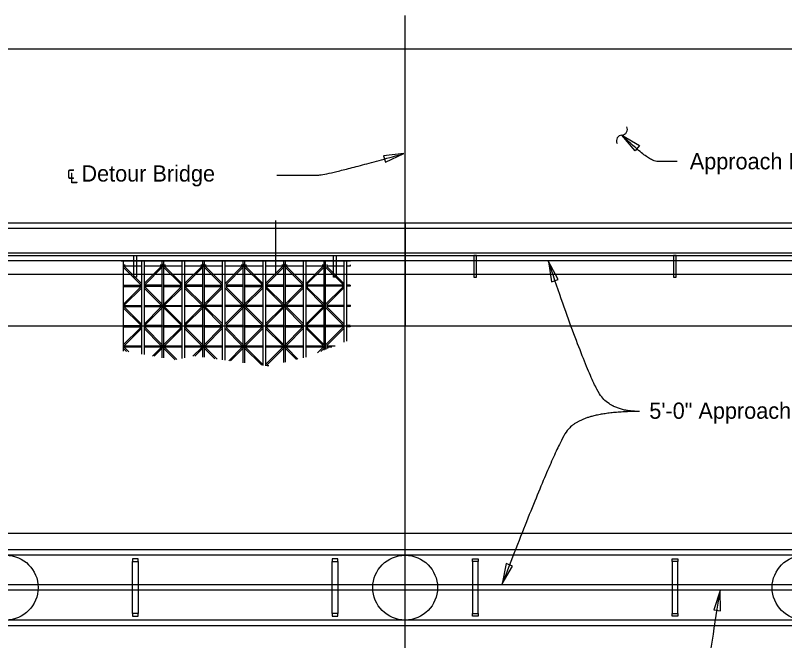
# Model space of a CAD drawing. Extents: x -58 to 62, y 0 to 81.
# Drawn here: x 24.75 to 36.63, y 29.48 to 39.13 of the extents above; entities that cross this region are included whole.
import ezdxf

# ---------------------------------------------------------------- set-up
doc = ezdxf.new("R2010")
doc.units = 0
for name, color, linetype in [('CL_Minor', 7, 'Continuous'), ('Dimension', 7, 'Continuous'), ('SteelMisc', 7, 'Continuous'), ('SteelMisc_h', 7, 'Continuous'), ('Symbols', 7, 'Continuous'), ('TextStructures', 7, 'Continuous'), ('Wood_h', 7, 'Continuous')]:
    doc.layers.add(name, color=color, linetype=linetype)

msp = doc.modelspace()

# ---------------------------------------------------------------- linework, layer by layer
at = {"layer": 'CL_Minor'}
msp.add_lwpolyline([(30.77, 7.919), (30.77, 34.382), (30.77, 39.134)], dxfattribs=at)
at = {"layer": 'Dimension'}
for points in [[(34.321, 37.043), (34.118, 37.286), (34.39, 37.124)], [(30.752, 37.001), (30.437, 36.968), (30.465, 36.866)], [(32.982, 35.336), (33.032, 35.023), (33.132, 35.057)], [(32.269, 30.361), (32.43, 30.634), (32.331, 30.672)], [(35.633, 30.258), (35.534, 29.957), (35.638, 29.941)]]:
    msp.add_lwpolyline(points, close=True, dxfattribs=at)
for centre, start, end in [((34.112, 37.376), 273.732, 25.4592), ((34.123, 37.197), 93.732, 205.4592)]:
    msp.add_arc(centre, 0.0894, start, end, dxfattribs=at)
for points in [[(34.972, 36.881), (34.787, 36.881), (34.531, 36.881), (34.118, 37.286)], [(28.788, 36.667), (29.264, 36.667), (29.554, 36.667), (30.752, 37.001)], [(34.391, 33.02), (33.994, 33.02), (33.616, 33.469), (32.982, 35.336)], [(34.391, 33.02), (33.466, 33.02), (33.052, 32.395), (32.269, 30.361)]]:
    msp.add_open_spline(points, degree=2, dxfattribs=at)
at = {"layer": 'SteelMisc'}
for p, q in [((30.77, 35.926), (30.77, 34.343)), ((18.53, 35.468), (43.009, 35.468)), ((42.77, 35.343), (19.989, 35.343)), ((30.77, 29.718), (30.77, 30.885)), ((42.77, 30.343), (18.77, 30.343)), ((42.77, 30.259), (18.77, 30.259))]:
    msp.add_line(p, q, dxfattribs=at)
msp.add_lwpolyline([(18.765, 35.843), (18.53, 35.843), (18.53, 35.426), (43.009, 35.426)], dxfattribs=at)
at = {"layer": 'SteelMisc_h'}
for p, q in [((26.387, 35.343), (29.926, 35.343)), ((26.416, 35.343), (26.416, 33.952)), ((26.436, 35.289), (26.436, 35.256)), ((26.697, 35.343), (26.697, 33.907)), ((26.738, 35.343), (26.738, 33.899)), ((26.999, 35.255), (26.999, 35.289)), ((27.02, 33.85), (27.02, 35.343)), ((27.02, 35.298), (27.02, 35.246)), ((27.041, 35.343), (27.041, 33.846)), ((27.061, 35.289), (27.061, 35.257)), ((27.322, 35.343), (27.322, 33.839)), ((27.363, 35.343), (27.363, 33.847)), ((27.624, 35.255), (27.624, 35.289)), ((27.645, 33.859), (27.645, 35.343)), ((27.645, 35.298), (27.645, 35.247)), ((27.666, 35.343), (27.666, 33.856)), ((27.686, 35.29), (27.686, 35.257)), ((27.947, 35.343), (27.947, 33.818)), ((27.988, 35.343), (27.988, 33.812)), ((28.249, 35.256), (28.249, 35.29)), ((28.27, 33.773), (28.27, 35.343)), ((28.27, 35.299), (28.27, 35.247)), ((28.291, 35.343), (28.291, 33.77)), ((28.311, 35.29), (28.311, 35.258)), ((28.572, 35.343), (28.572, 33.731)), ((28.613, 35.343), (28.613, 33.725)), ((28.874, 35.256), (28.874, 35.29)), ((28.895, 33.776), (28.895, 35.343)), ((28.895, 35.299), (28.895, 35.248)), ((28.916, 35.343), (28.916, 33.781)), ((28.936, 35.291), (28.936, 35.258)), ((29.197, 35.343), (29.197, 33.849)), ((29.238, 35.343), (29.238, 33.859)), ((29.499, 35.257), (29.499, 35.291)), ((29.52, 33.967), (29.52, 35.343)), ((29.52, 35.3), (29.52, 35.248)), ((29.541, 33.975), (29.541, 35.343)), ((29.541, 35.249), (29.541, 35.3)), ((29.561, 35.291), (29.561, 35.258)), ((29.822, 35.343), (29.822, 34.09)), ((29.863, 35.343), (29.863, 34.107)), ((29.921, 35.285), (29.921, 35.264)), ((26.416, 35.247), (26.676, 34.987)), ((26.698, 34.995), (26.436, 35.256)), ((26.696, 35.262), (26.438, 35.262)), ((26.996, 35.262), (26.737, 35.262)), ((26.739, 34.995), (26.999, 35.255)), ((26.759, 34.986), (27.02, 35.246)), ((27.02, 34.674), (27.02, 35.246)), ((27.041, 35.248), (27.301, 34.988)), ((27.323, 34.995), (27.061, 35.257)), ((27.321, 35.263), (27.063, 35.263)), ((27.621, 35.263), (27.362, 35.263)), ((27.364, 34.995), (27.624, 35.255)), ((27.384, 34.986), (27.645, 35.247)), ((27.645, 34.674), (27.645, 35.247)), ((27.666, 35.248), (27.926, 34.988)), ((27.948, 34.996), (27.686, 35.257)), ((27.946, 35.263), (27.688, 35.263)), ((28.246, 35.263), (27.987, 35.263)), ((27.989, 34.996), (28.249, 35.256)), ((28.009, 34.987), (28.27, 35.247)), ((28.27, 34.675), (28.27, 35.247)), ((28.291, 35.249), (28.551, 34.989)), ((28.573, 34.996), (28.311, 35.258)), ((28.571, 35.264), (28.313, 35.264)), ((28.871, 35.264), (28.612, 35.264)), ((28.614, 34.996), (28.874, 35.256)), ((28.634, 34.987), (28.895, 35.248)), ((28.895, 34.675), (28.895, 35.248)), ((28.916, 35.249), (29.176, 34.989)), ((29.198, 34.997), (28.936, 35.258)), ((29.196, 35.264), (28.938, 35.264)), ((29.496, 35.264), (29.237, 35.264)), ((29.239, 34.997), (29.499, 35.257)), ((29.259, 34.988), (29.52, 35.248)), ((29.52, 34.676), (29.52, 35.248)), ((29.801, 34.989), (29.541, 35.249)), ((29.822, 34.998), (29.561, 35.258)), ((29.824, 35.264), (29.562, 35.264)), ((29.921, 35.264), (29.863, 35.264)), ((26.676, 34.933), (26.416, 34.673)), ((26.417, 34.97), (26.675, 34.97)), ((26.42, 34.95), (26.677, 34.95)), ((26.697, 34.924), (26.436, 34.664)), ((26.676, 34.987), (26.676, 34.933)), ((26.739, 34.925), (26.999, 34.665)), ((26.759, 34.986), (26.759, 34.934)), ((27.02, 34.97), (26.759, 34.97)), ((26.759, 34.934), (27.02, 34.674)), ((27.018, 34.95), (26.76, 34.95)), ((27.301, 34.933), (27.041, 34.673)), ((27.042, 34.971), (27.3, 34.971)), ((27.045, 34.95), (27.302, 34.95)), ((27.322, 34.925), (27.061, 34.664)), ((27.301, 34.988), (27.301, 34.933)), ((27.364, 34.926), (27.624, 34.666)), ((27.384, 34.986), (27.384, 34.935)), ((27.645, 34.971), (27.384, 34.971)), ((27.384, 34.935), (27.645, 34.674)), ((27.643, 34.95), (27.385, 34.95)), ((27.926, 34.934), (27.666, 34.674)), ((27.667, 34.971), (27.925, 34.971)), ((27.67, 34.951), (27.927, 34.951)), ((27.947, 34.925), (27.686, 34.665)), ((27.926, 34.988), (27.926, 34.934)), ((27.989, 34.926), (28.249, 34.666)), ((28.009, 34.987), (28.009, 34.935)), ((28.27, 34.971), (28.009, 34.971)), ((28.009, 34.935), (28.27, 34.675)), ((28.268, 34.951), (28.01, 34.951)), ((28.551, 34.935), (28.291, 34.674)), ((28.292, 34.972), (28.55, 34.972)), ((28.295, 34.951), (28.552, 34.951)), ((28.572, 34.926), (28.311, 34.665)), ((28.551, 34.989), (28.551, 34.935)), ((28.614, 34.927), (28.874, 34.667)), ((28.634, 34.987), (28.634, 34.936)), ((28.895, 34.972), (28.634, 34.972)), ((28.634, 34.936), (28.895, 34.675)), ((28.893, 34.951), (28.635, 34.951)), ((29.176, 34.935), (28.916, 34.675)), ((28.917, 34.972), (29.175, 34.972)), ((28.92, 34.952), (29.177, 34.952)), ((29.197, 34.926), (28.936, 34.666)), ((29.176, 34.989), (29.176, 34.935)), ((29.239, 34.927), (29.499, 34.667)), ((29.259, 34.988), (29.259, 34.936)), ((29.52, 34.972), (29.259, 34.972)), ((29.259, 34.936), (29.52, 34.676)), ((29.518, 34.952), (29.26, 34.952)), ((29.801, 34.935), (29.541, 34.675)), ((29.797, 34.931), (29.541, 34.675)), ((29.8, 34.952), (29.544, 34.952)), ((29.799, 34.972), (29.545, 34.972)), ((29.823, 34.927), (29.561, 34.666)), ((29.801, 34.989), (29.801, 34.935)), ((29.921, 34.972), (29.863, 34.972)), ((29.921, 34.952), (29.864, 34.952)), ((29.921, 34.972), (29.921, 34.952)), ((26.416, 34.673), (26.492, 34.749)), ((27.041, 34.673), (27.117, 34.75)), ((27.666, 34.674), (27.742, 34.75)), ((28.291, 34.674), (28.367, 34.751)), ((28.916, 34.675), (28.992, 34.751)), ((26.416, 34.622), (26.676, 34.362)), ((26.436, 34.664), (26.436, 34.631)), ((26.698, 34.37), (26.436, 34.631)), ((26.438, 34.658), (26.697, 34.658)), ((26.696, 34.637), (26.438, 34.637)), ((26.996, 34.637), (26.737, 34.637)), ((26.739, 34.37), (26.999, 34.63)), ((26.74, 34.658), (27, 34.658)), ((26.759, 34.361), (27.02, 34.621)), ((26.999, 34.63), (26.999, 34.664)), ((27.02, 34.673), (27.02, 34.621)), ((27.02, 34.049), (27.02, 34.621)), ((27.041, 34.623), (27.301, 34.363)), ((27.061, 34.664), (27.061, 34.632)), ((27.323, 34.37), (27.061, 34.632)), ((27.063, 34.658), (27.322, 34.658)), ((27.321, 34.638), (27.063, 34.638)), ((27.621, 34.638), (27.362, 34.638)), ((27.364, 34.37), (27.624, 34.63)), ((27.365, 34.658), (27.625, 34.658)), ((27.384, 34.361), (27.645, 34.622)), ((27.624, 34.63), (27.624, 34.664)), ((27.645, 34.673), (27.645, 34.622)), ((27.645, 34.049), (27.645, 34.622)), ((27.666, 34.623), (27.926, 34.363)), ((27.686, 34.665), (27.686, 34.632)), ((27.948, 34.371), (27.686, 34.632)), ((27.688, 34.659), (27.947, 34.659)), ((27.946, 34.638), (27.688, 34.638)), ((28.246, 34.638), (27.987, 34.638)), ((27.989, 34.371), (28.249, 34.631)), ((27.99, 34.659), (28.25, 34.659)), ((28.009, 34.362), (28.27, 34.622)), ((28.249, 34.631), (28.249, 34.665)), ((28.27, 34.674), (28.27, 34.622)), ((28.27, 34.05), (28.27, 34.622)), ((28.291, 34.624), (28.551, 34.364)), ((28.311, 34.665), (28.311, 34.633)), ((28.573, 34.371), (28.311, 34.633)), ((28.313, 34.659), (28.572, 34.659)), ((28.571, 34.639), (28.313, 34.639)), ((28.871, 34.639), (28.612, 34.639)), ((28.614, 34.371), (28.874, 34.631)), ((28.615, 34.659), (28.875, 34.659)), ((28.634, 34.362), (28.895, 34.623)), ((28.874, 34.631), (28.874, 34.665)), ((28.895, 34.674), (28.895, 34.623)), ((28.895, 34.05), (28.895, 34.623)), ((28.916, 34.624), (29.176, 34.364)), ((28.936, 34.666), (28.936, 34.633)), ((29.198, 34.372), (28.936, 34.633)), ((28.938, 34.66), (29.197, 34.66)), ((29.196, 34.639), (28.938, 34.639)), ((29.496, 34.639), (29.237, 34.639)), ((29.239, 34.372), (29.499, 34.632)), ((29.24, 34.66), (29.5, 34.66)), ((29.259, 34.363), (29.52, 34.623)), ((29.499, 34.632), (29.499, 34.666)), ((29.52, 34.675), (29.52, 34.623)), ((29.52, 34.051), (29.52, 34.623)), ((29.541, 34.624), (29.541, 34.675)), ((29.801, 34.364), (29.541, 34.624)), ((29.561, 34.666), (29.561, 34.633)), ((29.822, 34.373), (29.561, 34.633)), ((29.824, 34.639), (29.562, 34.639)), ((29.564, 34.66), (29.824, 34.66)), ((29.863, 34.66), (29.926, 34.66)), ((29.921, 34.639), (29.863, 34.639)), ((29.921, 34.66), (29.921, 34.639)), ((26.417, 34.345), (26.675, 34.345)), ((26.676, 34.362), (26.676, 34.308)), ((26.759, 34.361), (26.759, 34.309)), ((27.02, 34.345), (26.759, 34.345)), ((27.042, 34.346), (27.3, 34.346)), ((27.301, 34.363), (27.301, 34.308)), ((27.384, 34.361), (27.384, 34.31)), ((27.645, 34.346), (27.384, 34.346)), ((27.667, 34.346), (27.925, 34.346)), ((27.926, 34.363), (27.926, 34.309)), ((28.009, 34.362), (28.009, 34.31)), ((28.27, 34.346), (28.009, 34.346)), ((28.292, 34.347), (28.55, 34.347)), ((28.551, 34.364), (28.551, 34.31)), ((28.634, 34.362), (28.634, 34.311)), ((28.895, 34.347), (28.634, 34.347)), ((28.917, 34.347), (29.175, 34.347)), ((29.176, 34.364), (29.176, 34.31)), ((29.259, 34.363), (29.259, 34.311)), ((29.52, 34.347), (29.259, 34.347)), ((29.799, 34.347), (29.545, 34.347)), ((29.801, 34.364), (29.801, 34.31)), ((29.921, 34.347), (29.863, 34.347)), ((29.921, 34.347), (29.921, 34.327)), ((26.676, 34.308), (26.416, 34.048)), ((26.42, 34.325), (26.677, 34.325)), ((26.697, 34.299), (26.436, 34.039)), ((26.739, 34.3), (26.999, 34.04)), ((26.759, 34.309), (27.02, 34.049)), ((27.018, 34.325), (26.76, 34.325)), ((27.301, 34.308), (27.041, 34.048)), ((27.045, 34.325), (27.302, 34.325)), ((27.322, 34.3), (27.061, 34.039)), ((27.364, 34.301), (27.624, 34.041)), ((27.384, 34.31), (27.645, 34.049)), ((27.643, 34.325), (27.385, 34.325)), ((27.926, 34.309), (27.666, 34.049)), ((27.67, 34.326), (27.927, 34.326)), ((27.947, 34.3), (27.686, 34.04)), ((27.989, 34.301), (28.249, 34.041)), ((28.009, 34.31), (28.27, 34.05)), ((28.268, 34.326), (28.01, 34.326)), ((28.551, 34.31), (28.291, 34.049)), ((28.295, 34.326), (28.552, 34.326)), ((28.572, 34.301), (28.311, 34.04)), ((28.614, 34.302), (28.874, 34.042)), ((28.634, 34.311), (28.895, 34.05)), ((28.893, 34.326), (28.635, 34.326)), ((29.176, 34.31), (28.916, 34.05)), ((28.92, 34.327), (29.177, 34.327)), ((29.197, 34.301), (28.936, 34.041)), ((29.239, 34.302), (29.499, 34.042)), ((29.259, 34.311), (29.52, 34.051)), ((29.518, 34.327), (29.26, 34.327)), ((29.801, 34.31), (29.541, 34.05)), ((29.797, 34.306), (29.541, 34.05)), ((29.8, 34.327), (29.544, 34.327)), ((29.823, 34.302), (29.561, 34.041)), ((29.921, 34.327), (29.864, 34.327)), ((26.416, 34.048), (26.492, 34.124)), ((27.041, 34.048), (27.117, 34.125)), ((27.666, 34.049), (27.742, 34.125)), ((28.291, 34.049), (28.367, 34.126)), ((28.916, 34.05), (28.992, 34.126)), ((26.416, 33.997), (26.469, 33.944)), ((26.436, 34.039), (26.436, 34.006)), ((26.503, 33.939), (26.436, 34.006)), ((26.438, 34.033), (26.697, 34.033)), ((26.696, 34.012), (26.438, 34.012)), ((26.996, 34.012), (26.737, 34.012)), ((26.74, 34.033), (27, 34.033)), ((26.87, 33.876), (26.999, 34.005)), ((26.895, 33.872), (27.02, 33.996)), ((26.999, 34.005), (26.999, 34.039)), ((27.02, 34.048), (27.02, 33.996)), ((27.041, 33.998), (27.221, 33.818)), ((27.061, 34.039), (27.061, 34.007)), ((27.245, 33.823), (27.061, 34.007)), ((27.063, 34.033), (27.322, 34.033)), ((27.321, 34.013), (27.063, 34.013)), ((27.621, 34.013), (27.362, 34.013)), ((27.365, 34.033), (27.625, 34.033)), ((27.492, 33.874), (27.624, 34.005)), ((27.524, 33.876), (27.645, 33.997)), ((27.624, 34.005), (27.624, 34.039)), ((27.645, 34.048), (27.645, 33.997)), ((27.666, 33.998), (27.83, 33.834)), ((27.686, 34.04), (27.686, 34.007)), ((27.865, 33.829), (27.686, 34.007)), ((27.688, 34.034), (27.947, 34.034)), ((27.946, 34.013), (27.688, 34.013)), ((28.246, 34.013), (27.987, 34.013)), ((27.99, 34.034), (28.25, 34.034)), ((28.047, 33.804), (28.249, 34.006)), ((28.073, 33.8), (28.27, 33.997)), ((28.249, 34.006), (28.249, 34.04)), ((28.27, 34.049), (28.27, 33.997)), ((28.291, 33.999), (28.551, 33.739)), ((28.311, 34.04), (28.311, 34.008)), ((28.573, 33.746), (28.311, 34.008)), ((28.313, 34.034), (28.572, 34.034)), ((28.571, 34.014), (28.313, 34.014)), ((28.871, 34.014), (28.612, 34.014)), ((28.614, 33.746), (28.874, 34.006)), ((28.615, 34.034), (28.875, 34.034)), ((28.634, 33.737), (28.895, 33.998)), ((28.874, 34.006), (28.874, 34.04)), ((28.895, 34.049), (28.895, 33.998)), ((28.916, 33.999), (29.092, 33.824)), ((28.936, 34.041), (28.936, 34.008)), ((29.115, 33.829), (28.936, 34.008)), ((28.938, 34.035), (29.197, 34.035)), ((29.196, 34.014), (28.938, 34.014)), ((29.496, 34.014), (29.237, 34.014)), ((29.24, 34.035), (29.5, 34.035)), ((29.416, 33.924), (29.499, 34.007)), ((29.466, 33.945), (29.52, 33.998)), ((29.499, 34.007), (29.499, 34.041)), ((29.52, 34.05), (29.52, 33.998)), ((29.52, 33.967), (29.52, 33.998)), ((29.541, 33.999), (29.541, 34.05)), ((29.558, 33.982), (29.541, 33.999)), ((29.561, 34.041), (29.561, 34.008)), ((29.579, 33.991), (29.561, 34.008)), ((29.636, 34.014), (29.562, 34.014)), ((29.564, 34.035), (29.687, 34.035)), ((28.551, 33.739), (28.551, 33.734)), ((28.634, 33.737), (28.634, 33.722)), ((28.667, 33.722), (28.637, 33.722))]:
    msp.add_line(p, q, dxfattribs=at)
for points in [[(42.704, 35.926), (18.866, 35.926)], [(42.671, 35.843), (18.868, 35.843)], [(18.767, 34.343), (42.77, 34.343)], [(42.627, 30.885), (18.911, 30.885)], [(18.77, 29.718), (42.77, 29.718)]]:
    msp.add_lwpolyline(points, dxfattribs=at)
for points in [[(26.582, 35.426), (26.624, 35.426), (26.624, 35.093), (26.582, 35.093)], [(29.666, 35.426), (29.707, 35.426), (29.707, 35.093), (29.666, 35.093)], [(31.874, 35.426), (31.832, 35.426), (31.832, 35.093), (31.874, 35.093)], [(34.957, 35.426), (34.916, 35.426), (34.916, 35.093), (34.957, 35.093)], [(26.645, 30.702), (26.645, 30.744), (26.562, 30.744), (26.562, 30.702)], [(26.562, 29.9), (26.562, 30.702), (26.645, 30.702), (26.645, 29.9)], [(29.728, 30.702), (29.728, 30.744), (29.645, 30.744), (29.645, 30.702)], [(29.645, 29.9), (29.645, 30.702), (29.728, 30.702), (29.728, 29.9)], [(31.811, 30.702), (31.811, 30.744), (31.895, 30.744), (31.895, 30.702)], [(31.895, 29.9), (31.895, 30.702), (31.811, 30.702), (31.811, 29.9)], [(34.895, 30.702), (34.895, 30.744), (34.978, 30.744), (34.978, 30.702)], [(34.978, 29.9), (34.978, 30.702), (34.895, 30.702), (34.895, 29.9)], [(26.645, 29.859), (26.645, 29.9), (26.562, 29.9), (26.562, 29.859)], [(29.728, 29.859), (29.728, 29.9), (29.645, 29.9), (29.645, 29.859)], [(31.811, 29.859), (31.811, 29.9), (31.895, 29.9), (31.895, 29.859)], [(34.895, 29.859), (34.895, 29.9), (34.978, 29.9), (34.978, 29.859)]]:
    msp.add_lwpolyline(points, close=True, dxfattribs=at)
at = {"layer": 'Symbols'}
for points in [[(30.77, 38.614), (24.46, 38.614), (24.46, 38.459), (24.325, 38.769), (24.325, 38.614), (18.222, 38.614)], [(43.369, 38.614), (38.125, 38.614), (38.125, 38.459), (37.99, 38.769), (37.99, 38.614), (30.77, 38.614)]]:
    msp.add_lwpolyline(points, dxfattribs=at)
at = {"layer": 'TextStructures'}
msp.add_open_spline([(34.419, 26.464), (34.802, 26.464), (35.01, 26.64), (35.162, 27.159), (35.633, 30.258)], degree=2, dxfattribs=at)
at = {"layer": 'Wood_h'}
for p, q in [((28.77, 35.968), (28.77, 35.134)), ((43.52, 35.134), (18.02, 35.134)), ((45.861, 31.135), (15.283, 31.135)), ((44.645, 30.801), (16.932, 30.801)), ((44.669, 29.801), (16.932, 29.801))]:
    msp.add_line(p, q, dxfattribs=at)
for centre in [(24.603, 30.301), (30.77, 30.301), (36.937, 30.301)]:
    msp.add_circle(centre, 0.5, dxfattribs=at)

# ---------------------------------------------------------------- texts
at = {"layer": 'Dimension'}
for s, p in [('Approach Roadway ', (35.165, 36.758)), ('5\'-0" Approach Span', (34.54, 32.907))]:
    msp.add_text(s, height=0.25, dxfattribs=at).set_placement(p)
at = {"layer": 'TextStructures'}
msp.add_text('℄ Detour Bridge', height=0.25, dxfattribs=at).set_placement((25.543, 36.569))

doc.saveas('drawing.dxf')
